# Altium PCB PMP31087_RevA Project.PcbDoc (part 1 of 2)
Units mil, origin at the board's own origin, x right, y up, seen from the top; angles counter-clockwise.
Board outline 6012.5 x 1662.5 mil, 2 copper layers (Top Layer, Bottom Layer), stack 62 mil thick; 71 components, 40 nets, 159 pads, 54 vias.
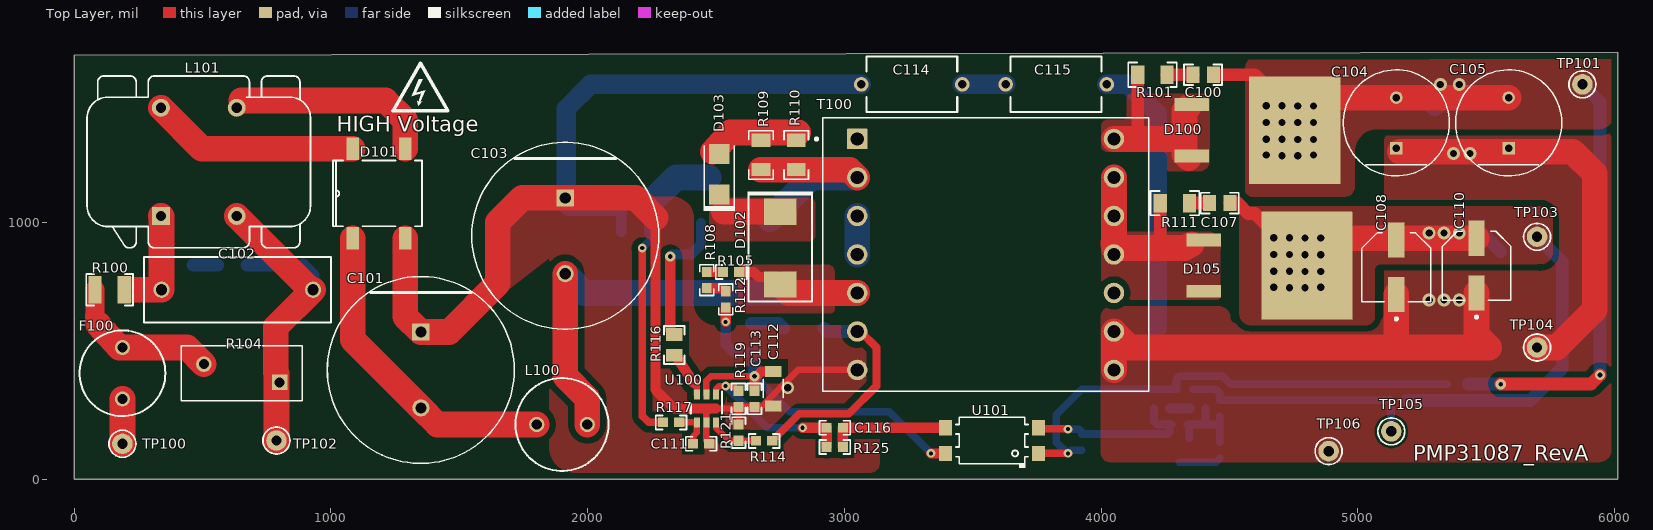
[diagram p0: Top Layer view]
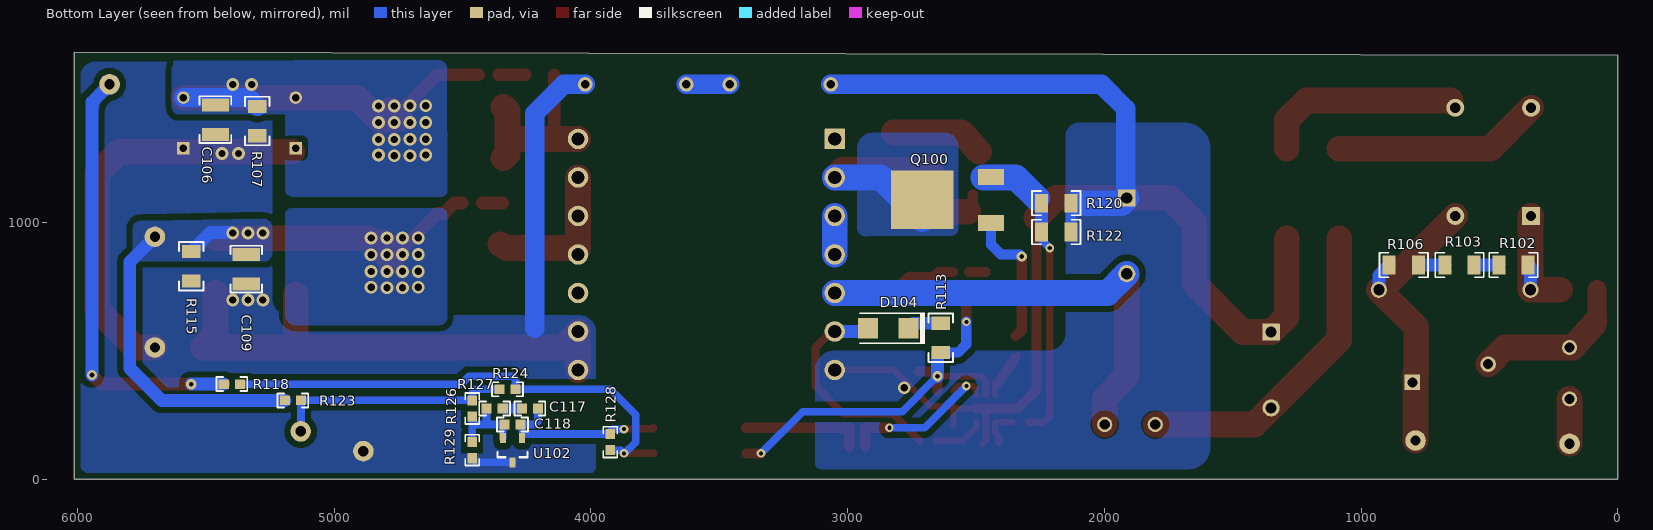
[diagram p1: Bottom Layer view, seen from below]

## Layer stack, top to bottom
Top Solder: solder mask 0.4, Solder Resist, Dk 3.5
Top Layer: signal copper 1.4
Dielectric1: core 59.2, FR-4 High Tg, Dk 4.8
Bottom Layer: signal copper 1.4
Bottom Solder: solder mask 0.4, Solder Resist, Dk 3.5

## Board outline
0,0 0,1650 6012.5,1662.5 6012.5,0

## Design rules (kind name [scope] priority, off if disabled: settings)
AcuteAngle [All] p1: minimum=4.50000000000000E+0001 checktracksonly=FALSE
AssemblyTestPointUsage [All] p1: valid=2
BoardOutlineClearance BoardOutlineClearance_MountingHoles [OnCopper and InComponentClass('Mounting Holes')] p1: gap=39.37 ignorepadtopadclearanceinfootprint=FALSE
BoardOutlineClearance BoardOutlineClearance_Poly [OnCopper and IsPoly] p2: gap=25 ignorepadtopadclearanceinfootprint=FALSE
BoardOutlineClearance [OnCopper and Not InComponentClass('Logo') and not InComponentClass('FiducialMark') and not InRegion(1000,500,4000,800) and not InPoly] p3: gap=40 ignorepadtopadclearanceinfootprint=FALSE
Clearance Clearance_Keepouts [((IsTrack Or IsArc) And Not InPoly) And IsFree and IsKeepOut vs ((IsTrack Or IsArc) And Not InPoly) And IsFree and IsKeepOut] p1: gap=0 ignorepadtopadclearanceinfootprint=FALSE
Clearance Clearance_Poly [InPolygon] p2: gap=25 ignorepadtopadclearanceinfootprint=TRUE
Clearance Clearance_FiducialMark [IsKeepOut and InComponentClass('FiducialMark') vs IsPad and InComponentClass('FiducialMark')] p3: gap=0 ignorepadtopadclearanceinfootprint=FALSE
Clearance [All] p4: gap=7.87 ignorepadtopadclearanceinfootprint=TRUE
ComponentClearance ComponentClearance_MountingHoles_FiducialMarks [InComponentClass('Mounting Holes') vs InComponentClass('FiducialMark')] p1: gap=50 collisioncheckmode=3 verticalgap=10 showdistances=FALSE
ComponentClearance ComponentClearance_Shunt [InComponentClass('Header') vs InComponentClass('Shunt')] p2: gap=0 collisioncheckmode=3 verticalgap=0 showdistances=FALSE
ComponentClearance ComponentClearance_Logo [InComponentClass('Logo')] p3: gap=30 collisioncheckmode=3 verticalgap=10 showdistances=FALSE
ComponentClearance ComponentClearance_ScrewToNut [(HasFootprint('NY PMS 440 0025 PH')) vs (HasFootprint('Keystone_1902C'))] p4: gap=5 collisioncheckmode=3 verticalgap=10 showdistances=FALSE
ComponentClearance ComponentClearance_MountingHoles [InComponentClass('Mounting Holes')] p5: gap=100 collisioncheckmode=3 verticalgap=100000 showdistances=FALSE
ComponentClearance ComponentClearance_SmallPassives [HasFootprint('0201*') or HasFootprint('0402*') or HasFootprint('0508') or HasFootprint('0603*') or HasFootprint('0612') or HasFootprint('0805*') or HasFootprint('0815*') or HasFootprint('0830*') or HasFootprint('1206*') or HasFootprint('1210*') or HasFootprint('1808*') or HasFootprint('1812*') or HasFootprint('1825*') or HasFootprint('2010*') or HasFootprint('2220*') or HasFootprint('2225*') or HasFootprint('2512*') or HasFootprint('2728*') or HasFootprint('3518*') vs HasFootprint('0201*') or HasFootprint('0402*') or HasFootprint('0508') or HasFootprint('0603*') or HasFootprint('0612') or HasFootprint('0805*') or HasFootprint('0815*') or HasFootprint('0830*') or HasFootprint('1206*') or HasFootprint('1210*') or HasFootprint('1808*') or HasFootprint('1812*') or HasFootprint('1825*') or HasFootprint('2010*') or HasFootprint('2220*') or HasFootprint('2225*') or HasFootprint('2512*') or HasFootprint('2728*') or HasFootprint('3518*')] p6: gap=14.96 collisioncheckmode=3 verticalgap=10 showdistances=FALSE
ComponentClearance ComponentClearance_THtoSMT [IsThruComponent vs IsSMTComponent] p7: gap=30 collisioncheckmode=3 verticalgap=30 showdistances=FALSE
ComponentClearance ComponentClearance_THtoTH [IsThruComponent vs IsThruComponent] p8: gap=20 collisioncheckmode=3 verticalgap=30 showdistances=FALSE
ComponentClearance [All] p9: gap=20 collisioncheckmode=3 verticalgap=10 showdistances=FALSE
DiffPairsRouting [All] p1: maxlimit=100 minlimit=10 mostfreqgap=10 toplayer_minwidth=15 toplayer_maxwidth=15 toplayer_prefwidth=15 bottomlayer_minwidth=15 bottomlayer_maxwidth=15 bottomlayer_prefwidth=15 maxuncoupledlength=1000
FabricationTestPointUsage TestPointUsage [All] p1: valid=2 allowmultiple=FALSE
FabricationTestpoint Testpoint [All] p1: side=3 testpointundercomponent=TRUE minsize=40 maxsize=100 preferedsize=60 minholesize=0 maxholesize=40 preferedholesize=32 testpointgrid=1 allowsidetop=TRUE allowsidebottom=TRUE usegrid=TRUE gridtolerance=0.01
FanoutControl Fanout_LCC [IsLCC] p1: bgadir=Out bgaviamode=Centered fanoutstyle=Auto fanoutdirection=Alternating viagrid=1 // Fanout_LCC (Default Rule)
FanoutControl Fanout_BGA [IsBGA] p2: bgadir=Out bgaviamode=Centered fanoutstyle=Auto fanoutdirection=Alternating viagrid=1 // Fanout_BGA (Default Rule)
FanoutControl Fanout_Default [All] p4: bgadir=Out bgaviamode=Centered fanoutstyle=Auto fanoutdirection=Alternating viagrid=1 // Fanout_Default (Default Rule)
FanoutControl Fanout_Small [(CompPinCount < 5)] p5: bgadir=Out bgaviamode=Centered fanoutstyle=Auto fanoutdirection=OutThenIn viagrid=1 // Fanout_Small (Default Rule)
Height [All] p1: minheight=0 maxheight=1500 prefheight=500
HoleSize [All] p1: absolutevalues=TRUE maxlimit=251 minlimit=7.87 maxpercent=80.000 minpercent=20.000
MinimumAnnularRing MinimumAnnularRing_ThermalPadVias [IsVia and InAnyComponent] p1: minimumring=5.91
MinimumAnnularRing [All] p2: minimumring=7.87
MinimumSolderMaskSliver MinimumSolderMaskSliver_Logo [InComponentClass('Logo') vs InComponentClass('Logo')] p1: minsoldermaskwidth=0.7
MinimumSolderMaskSliver [All] p2: minsoldermaskwidth=3.94
PlaneConnect [All] p1: planeconnectstyle=Relief reliefexpansion=10 reliefentries=4 reliefconductorwidth=10 reliefairgap=10
PolygonConnect [All] p1: connectstyle=Direct reliefconductorwidth=10 reliefentries=4 polygonreliefangle="90 Angle" airgapwidth=10
RoutingVias ThermalPadVias [IsVia and InAnyComponent] p1: holewidth=7.87 width=19.68 viastyle="Through Hole" minholewidth=7.87 minwidth=19.68 maxholewidth=12.99 maxwidth=23.62
RoutingVias [All] p2: holewidth=16 width=34 viastyle="Through Hole" minholewidth=7.87 minwidth=24 maxholewidth=40 maxwidth=65
SilkToBoardRegionClearance [Not ((IsComment or IsDesignator) And (Hide <> 'False')) and not InRegion(1000,500,4000,800)] p1:
SilkToSilkClearance SilkToSilkClearance_Pb-FreeLogo [(HasFootprint('Pb-Free_Overlay_Medium') OR HasFootprint('Pb-Free_Overlay_Small')) vs (HasFootprint('Pb-Free_Overlay_Medium') OR HasFootprint('Pb-Free_Overlay_Small'))] p1 off: silktosilkclearance=0
SilkToSilkClearance [All] p2 off: silktosilkclearance=3.94
SilkToSolderMaskClearance SilkToComponentPadClearance [(IsPad or IsFill or IsRegion) and InAnycomponent] p1: minsilkscreentomaskgap=5 clearancetoexposedcopper=TRUE
SilkToSolderMaskClearance "Silk to Solder Mask Opening" [All] p2: minsilkscreentomaskgap=3.94 clearancetoexposedcopper=FALSE
SolderMaskExpansion [All] p1: expansion=1.97 istentingtop=FALSE
UnRoutedNet [All] p1: checkbadconnections=TRUE
Width [All] p1: maxlimit=100 minlimit=6 preferedwidth=10 checkconnectedcopper=TRUE
13 further rules are at their usual default settings.

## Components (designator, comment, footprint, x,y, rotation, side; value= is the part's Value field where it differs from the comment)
C100 "" 0805_HV 4397.5,1575 r0 top
C101 "860241381004" FP-860241381004_RADIAL-MFG 1350,425 r270 top value=33µF
C102 "890324025027CS" WCAP-FTX2_1800x600x1150 635.14,737.5 r0 top value=0.22uF
C103 "860241381004" FP-860241381004_RADIAL-MFG 1912.5,947.64 r270 top value=33µF
C104 "25ZL680MEFC10X20" FP-25ZL680MEFC10X20_RADIAL-MFG 5150,1387.5 r90 top value=680µF
C105 "25ZL680MEFC10X20" FP-25ZL680MEFC10X20_RADIAL-MFG 5587.5,1387.5 r90 top value=680µF
C106 "GRM32RR71H105KA01L" 1210_200 5462.5,1400 r270 bottom value=DNP
C107 "" 0805_HV 4462.5,1075 r0 top
C108 "DNP" FP-APXJ100ARA391MFA0G_SMD2-MFG 5150,825 r90 top
C109 "GRM32RR71H105KA01L" 1210_200 5342.57,817.38 r270 bottom value=DNP
C110 "APXJ100ARA391MFA0G" FP-APXJ100ARA391MFA0G_SMD2-MFG 5462.5,831.3 r90 top value=390µF
C111 "" 0603 2442.13,137.5 r0 top value=DNP
C112 "C3216X7R1H335K160AC" 1206_190 2722.8,352.2 r270 top value=3.3uF
C113 "C1608X7R1H104K080AA" 0603 2650,312.5 r270 top value=0.1uF
C114 "" C900_9x13 3262.5,1537.5 r180 top value=2200pF
C115 "C921U222MVVDBA7317" C900_9x13 3825,1537.5 r180 top value=2200pF
C116 "C0603C682K5RACTU" 0603 2962.5,200 r180 top value=6800pF
C117 "" 0603 4237.5,275 r0 bottom value=DNP
C118 "GRM188R71H224KAC4D" 0603 4305.41,212.5 r180 bottom value=0.22uF
D100 "MBRB20100CTT4G" DDPAK 4598.62,1358.73 r0 top value=100V
D101 "DF08SA" DF-S 1187.5,1112.5 r90 top value=800V
D102 "SMCJ110A" SMC_265 2750,900 r270 top value=110V
D103 "US1J-13-F" SMA 2512.5,1187.5 r90 top value=600V
D104 "US1D-E3/61T" SMA 2841.93,587.5 r0 bottom value=200V
D105 "MBRB2060CTT4G" DDPAK 4646.06,831.3 r0 top value=60V
F100 "37212000001" FUSE_372 187.5,412.2 r270 top
"HIGH Voltage" "DANGER HIGH VOLTAGE" IEC_HighVoltage_Small 1348.5,1522.5 r0 top
L100 "744732470" WE-TI_8075_STU 1900,212.5 r0 top value=47uH
L101 "744823220" WE-CMB_M 485.14,1235.63 r90 top value=20mH
Q100 "IPD60R600P7SAUMA1" DPAK 2575,1087.5 r0 bottom value=600V
R100 "CRCW12100000Z0EAHP" 1210 137.5,737.5 r0 top value=0
R101 "DNP" 1206 4200,1575 r180 top
R102 "CRCW12061M50JNEA" 1206 406,833.75 r180 bottom value=1.5Meg
R103 "CRCW12061M50JNEA" 1206 616.25,833.75 r180 bottom value=1.5Meg
R104 "B72210S2271K101" FP-B72210S2271K101_RADIAL-MFG 652.5,412.2 r180 top
R105 "CRCW06034M99FKEA" 0603 2558.9,806.5 r0 top value=4.99Meg
R106 "CRCW12061M50JNEA" 1206 833.75,833.75 r180 bottom value=1.5Meg
R107 "DNP" 1206 5300,1394.59 r90 bottom
R108 "CRCW06034M99FKEA" 0603 2463.9,775 r90 top value=4.99Meg
R109 "DNP" 1206 2675,1262.5 r90 top
R110 "RC1206FR-0749R9L" 1206 2812.5,1262.5 r90 top value=49.9
R111 "DNP" 1206 4287.5,1075 r180 top
R112 "CRCW06034M99FKEA" 0603 2537.5,700 r90 top value=4.99Meg
R113 "CRCW120622R0JNEA" 1206 2637.5,550 r270 bottom value=22
R114 "CRCW0603147KFKEA" 0603 2687.5,148.62 r0 top value=147k
R115 "DNP" 1206 5557.04,828.73 r90 bottom
R116 "CRCW080510R0JNEA" 0805_HV 2337.5,522.5 r90 top value=10
R117 "CRCW06031K69FKEA" 0603 2325,220.87 r180 top value=1.69k
R118 "CRCW06034K02FKEA" 0603 5398.67,369.75 r180 bottom value=DNP
R119 "CRCW06034K02FKEA" 0603 2587.5,312.5 r90 top value=4.02k
R120 "ERJ-8RQFR39V" 1206 2187.5,1075 r0 bottom value=0.39
R121 "CRCW060340K2FKEA" 0603 2587.5,180.51 r270 top value=40.2k
R122 "ERJ-8RQFR39V" 1206 2187.5,962.5 r0 bottom value=0.39
R123 "CRCW060349R9FKEA" 0603 5160.67,306.5 r0 bottom value=49.9
R124 "CRCW06031K00FKEA" 0603 4325,350 r0 bottom value=1.00k
R125 "CRCW060332K4FKEA" 0603 2962.5,125 r0 top value=32.4k
R126 "RC0603FR-0761K9L" 0603 4462.5,275 r90 bottom value=61.9k
R127 "CRCW06034K02FKEA" 0603 4375,275 r180 bottom value=DNP
R128 "CRCW06031K00FKEA" 0603 3925,144 r270 bottom value=1.00k
R129 "CRCW060320K0FKEA" 0603 4462.5,112.5 r90 bottom value=20.0k
T100 "750319816" FP-750319816_PTH_TRANSFORMER_32MM25_27MM05-MFG 3550,875 r0 top
TP100 "5000" Keystone5000 187.5,137.5 r0 top
TP101 "5000" Keystone5000 5875,1537.5 r0 top
TP102 "5000" Keystone5000 787.5,150 r0 top
TP103 "5000" Keystone5000 5698.5,943.75 r0 top
TP104 "5001" Keystone5001 5698.5,512.5 r0 top
TP105 "5000" Keystone5000 5130.5,185.71 r90 top
TP106 "5001" Keystone5001 4886.5,108.75 r90 top
U100 "UCC28742DBVR" DBV0006A_N 2462.5,275 r270 top
U101 "FOD817ASD" N04C 3575,150 r180 top
U102 "ATL431LIBQDBZR" DBZ0003A_N 4305.41,112.5 r270 bottom

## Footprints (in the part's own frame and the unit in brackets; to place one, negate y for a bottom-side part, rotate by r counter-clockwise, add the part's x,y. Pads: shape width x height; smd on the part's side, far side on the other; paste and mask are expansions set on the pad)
0603 [mm] "0603 from SM-752 data"
  rect 1x0.95 smd: 1(-0.8,0) 2(0.8,0)
  silkscreen extent -1.52,-0.69 1.52,0.69, body extent -0.87,-0.47 0.87,0.47, height 1
0805_HV [mil] "0805 with 30mil clearance between pads"
  rect 50x63 smd: 1(-40,0) 2(40,0)
  silkscreen extent -74,-40 74,40, body extent -43,-29 43,29, height 57
1206 [mm] "1206 from SM-752 data"
  rect 1.3x1.85 smd: 1(-1.45,0) 2(1.45,0)
  silkscreen extent -2.4,-1.21 2.4,1.21, body extent -1.7,-0.9 1.7,0.9, height 1.35
1206_190 [mm] "1206_190"
  rect 1.1x1.6 smd: 1(-1.7,0) 2(1.7,0)
  silkscreen extent -0.9,-1 0.9,1, body extent -1.75,-0.95 1.75,0.95, height 1.9
1210 [mm] "1210 from SM-752 data"
  rect 1.3x2.7 smd: 1(-1.45,0) 2(1.45,0)
  silkscreen extent -2.32,-1.57 2.32,1.57, body extent -1.7,-1.35 1.7,1.35, height 1.35
1210_200 [mm] "1210"
  rect 1.3x2.7 smd: 1(-1.45,0) 2(1.45,0)
  silkscreen extent -2.32,-1.57 2.32,1.57, body extent -1.7,-1.35 1.7,1.35, height 2
C900_9x13 [mm] "Kemet"
  round 1.45 hole 0.85: 1(-5,0) 2(5,0)
  silkscreen extent -4.5,-2.75 4.5,2.75, body extent -4.49,-2.75 4.49,2.75, height 12.96
DBV0006A_N [mm] "SOT23, 6-Leads, Body 2.9x1.6mm, Pitch 0.95mm, Lead Span 2.8mm, IPC Medium Density"
  rrect17% 1x0.6 smd: 1(-1.375,0.95) 2(-1.375,0) 3(-1.375,-0.95) 4(1.375,-0.95) 5(1.375,0) 6(1.375,0.95)
  silkscreen extent -1.68,-1.55 0.5,1.55, body extent -1.42,-1.46 1.42,1.46, height 1.12
DBZ0003A_N [mm] "SOT23, 3-Leads, Body 2.9x1.3mm, Pitch 0.95mm, Lead Span 2.4mm, IPC Medium Density"
  rrect17% 1x0.6 smd: 1(-1.2,0.95) 2(-1.2,-0.95) 3(1.2,0)
  silkscreen extent 0.2,-1.5 0.7,1.5, body extent -1.26,-1.46 1.26,1.46, height 0.98
DDPAK [mil] "D2-PAK, 3-Pads, Body 9.7x10.4mm (max), TO-263AB, using Vishay Silionix recommended pad sizes"
  rrect8% 135x49.49 smd: 1(-246.06,100) 3(-246.06,-100)
  rrect1% 355x420 smd paste-181.1: 2(155.51,0)
  body extent -295,-202 324,202, height 180
DF-S [mil] "Diodes Inc. recommended land pattern per ap02001.pdf rev 30"
  rect 88x49 smd: 1(-174.5,102.36) 2(-174.5,-102.36) 3(174.5,-102.36) 4(174.5,102.36)
  silkscreen extent -128,-168 128,180, body extent -205,-168 205,168, height 108
DPAK [mm] "D-PAK, 3-Pads, Body 6.22x6.73mm (max), TO-252AA using nominal STEP model"
  rrect6% 2.6x1.6 smd: 1(-3.4,2.28) 3(-3.4,-2.28)
  rrect2% 6.2x5.8 smd paste-3: 2(3.4,0)
  body extent -3.86,-3.29 5.84,3.29, height 2.48
FP-25ZL680MEFC10X20_RADIAL-MFG [mm]
  rrect8% 1.25x1.25 hole 0.75 paste-1000 mask+0: 1(-2.5,0)
  round 1.25 hole 0.75 paste-1000 mask+0: 2(2.5,0)
  silkscreen extent -5.25,-5.25 5.25,5.25, body extent -5.35,-5.35 5.35,5.35, height 0.25
FP-750319816_PTH_TRANSFORMER_32MM25_27MM05-MFG [mm]
  rrect5% 2.02x2.02 hole 1.32 paste-1000 mask+0: 1(-12.7,11.43)
  round 2.02 hole 1.32 paste-1000 mask+0: 2(-12.7,7.62) 3(-12.7,3.81) 4(-12.7,0) 5(-12.7,-3.81) 6(-12.7,-7.62) 7(-12.7,-11.43) 8(12.7,-11.43) 9(12.7,-7.62) 10(12.7,-3.81) 11(12.7,0) 12(12.7,3.81) 13(12.7,7.62) 14(12.7,11.43)
  silkscreen extent -16.85,-13.52 16.12,13.52, body extent -16.22,-13.62 16.22,13.62, height 0.25
FP-860241381004_RADIAL-MFG [mm]
  rrect6% 1.7x1.7 hole 1.1 paste-1000 mask+0: 1(-3.75,0)
  round 1.7 hole 1.1 paste-1000 mask+0: 2(3.75,0)
  silkscreen extent -9.25,-9.25 9.25,9.25, body extent -9.35,-9.35 9.35,9.35, height 0.25
FP-APXJ100ARA391MFA0G_SMD2-MFG [mm]
  rrect6% 3.5x1.6 smd paste+0 mask+0: 1(-2.7,0) 2(2.7,0)
  silkscreen extent -5.22,-3.4 3.4,3.4, body extent -4.7,-3.65 4.7,3.65, height 0.25
FP-B72210S2271K101_RADIAL-MFG [mm]
  rrect6% 1.55x1.55 hole 1 paste-1000 mask+0: 1(-3.75,0.9)
  round 1.55 hole 1 paste-1000 mask+0: 2(3.75,-0.9)
  silkscreen extent -6,-2.7 6,2.7, body extent -6.1,-2.8 6.1,2.8, height 0.25
FUSE_372 [mm] "LITTELFUSE"
  round 1.5 hole 1: 1(-2.54,0) 2(2.54,0)
  silkscreen extent -4.25,-4.25 4.25,4.25, body extent -4.25,-4.25 4.25,4.25, height 8
IEC_HighVoltage_Small [mil]
  silkscreen extent -107,-88 107,97
Keystone5000 [mil] "For Keystone 500x miniature loop terminals"
  round 80 hole 40: 1(0,0)
  silkscreen extent -52,-52 52,52, body extent -49,-49 49,49, height 182
Keystone5001 [mil] "For Keystone 500x miniature loop terminals"
  round 80 hole 40: 1(0,0)
  silkscreen extent -52,-52 52,52, body extent -49,-49 49,49, height 182
N04C [mm] "FAIRCHILD"
  rect 1.3x1.5 smd mask+0.065: 1(-4.587,1.27) 2(-4.612,-1.27) 3(4.588,-1.27) 4(4.613,1.27)
  silkscreen extent -3.56,-2.3 3.56,2.72, body extent -5.08,-2.3 5.08,2.3, height 3.87
SMA [mm] "Molded Diode, 2-Leads, Body 4.3x2.6mm, IPC Medium Density, based on OnSemi component dimensions and land pattern"
  rect 2x2 smd: 1(-2,0) 2(2,0)
  silkscreen extent -3.66,-1.57 2.79,1.57, body extent -2.6,-1.3 2.6,1.3, height 2.42
SMC_265 [mm] "SMD, 2-Leads, Body 7.15x6.25mm"
  rect 2.6x3.2 smd: 1(-3.6,0) 2(3.6,0)
  silkscreen extent -5.6,-3.23 5.3,3.22, body extent -4.08,-3.13 4.08,3.13, height 2.65
WCAP-FTX2_1800x600x1150 [mm] "TH, 2-Leads, Body 18x6mm, Lead Spacing 15mm"
  round 1.6 hole 1.1: 1(-7.5,0) 2(7.5,0)
  silkscreen extent -9.25,-3.25 9.25,3.25, body extent -9.25,-3.25 9.25,3.25, height 12
WE-CMB_M [mil] "Wurth"
  rect 70x70 hole 40: 1(-210.63,147.64)
  round 70 hole 40: 2(-210.63,-147.64) 3(210.63,-147.64) 4(210.63,147.64)
  silkscreen extent -335,-435 335,435, body extent -335,-394 335,394, height 1044
WE-TI_8075_STU [mm] "TH, 2-Leads, Dia 9.5mm, Pin Spacing 5mm"
  round 1.5 hole 1: 1(-2.5,0) 2(2.5,0)
  silkscreen extent -4.6,-4.6 4.6,4.6, body extent -5.8,-5.8 5.8,5.8, height 9.7

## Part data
C100 C107: library part CMP-0008225-2, "CAP, CERM, +/- 10%, X7R, 0805", Cap_Case=0805, Manufacturer=MuRata, TempCo=X7R, Tolerance_%=10%, Value1=Unknown
C101 C103: library part CMP-0093307-1, "33 µF 400 V Aluminum Electrolytic Capacitors Radial, Can - 10000 Hrs @ 105°C", Digikey Part Number=732-9303-1-ND, Leakage Current=628uA, Manufacturer="Wurth Electronics", Mouser Part Number=710-860241381004, Operating Temperature Range="-25°C to +105°C", Tolerance_%=20%, ValueDisplayed=33uF
C102: library part CMP-0012315-3, "CAP, Film, 0.22 uF, 275 V, +/- 10%, TH", Cap_Case=18x11.5x6mm, Manufacturer="Wurth Elektronik", Supplier Part Number 1=732-5802-ND, Tolerance_%=10%, Value1=Unknown, Value2=275V, ValueDisplayed=0.22uF
C104 C105: library part CMP-0092158-1, "Aluminum Electrolytic Capacitors Radial, Can - 4000 Hrs @ 105°C 680UF 25V", Digikey Part Number=1189-3993-ND, Leakage Current=170uA, Manufacturer=Rubycon, Mouser Part Number=232-25ZL680MEFC10X20, Operating Temperature Range="-40°C to +105°C", Tolerance_%=20%, ValueDisplayed=680uF
C106 C109: library part CMP-0009251-1, "CAP, CERM, 1 uF, +/- 10%, X7R, 1210", Cap_Case=1210, Manufacturer=MuRata, Supplier Part Number 1=490-1863-1-ND, TempCo=X7R, Tolerance_%=10%, Value1="0.003 ohm", ValueDisplayed=DNP
C108: library part CMP-0092160-1, "Capacitors Radial", Digikey Part Number=565-APXJ100ARA391MFA0GCT-ND, Leakage Current=1950uA, Operating Temperature Range="-55°C to +105°C", Tolerance_%=20%
C110: library part CMP-0092160-1, "Aluminum - Polymer Capacitors Radial, Can - SMD 13mOhm 15000 Hrs @ 105°C", Digikey Part Number=565-APXJ100ARA391MFA0GCT-ND, Leakage Current=1950uA, Manufacturer="United Chemi-Con", Mouser Part Number=661-XJ100ARA391MFA0G, Operating Temperature Range="-55°C to +105°C", Tolerance_%=20%, ValueDisplayed=390uF
C111 C117: library part CMP-0007465-1, "CAP, CERM, +/- 10%, X7R, 0603", Cap_Case=0603, Manufacturer=MuRata, PartNumber=DNP, Supplier Part Number 1=490-1510-1-ND, TempCo=X7R, Tolerance_%=10%, Value1=Unknown
C112: library part CMP-0008700-1, "CAP, CERM, 3.3 uF, 50 V, +/- 10%, X7R, 1206_190", Cap_Case=1206, Manufacturer=TDK, Supplier Part Number 1=445-5990-1-ND, TempCo=X7R, Tolerance_%=10%, Value1=Unknown, Value2=50V, ValueDisplayed=3.3uF
C113: library part CMP-0007044-1, "CAP, CERM, 0.1 uF, 50 V, +/- 10%, X7R, 0603", Cap_Case=0603, Manufacturer=TDK, Supplier Part Number 1=445-1314-1-ND, TempCo=X7R, Tolerance_%=10%, Value1="0.0296 ohm", Value2=50V, ValueDisplayed=0.1uF
C114: library part CMP-0078358-1, "CAP, CERM, 2200 pF, X1 400 VAC/Y1 400 VAC, +/- 20%, Y5V, D9xL13mm", Cap_Case=9x13mm, Manufacturer=Kemet, Supplier Part Number 1=399-9487-1-ND, TempCo=Y5V, Tolerance_%=20%, ValueDisplayed=SHORT
C115: library part CMP-0078358-1, "CAP, CERM, 2200 pF, X1 400 VAC/Y1 400 VAC, +/- 20%, Y5V, D9xL13mm", Cap_Case=9x13mm, Manufacturer=Kemet, Supplier Part Number 1=399-9487-1-ND, TempCo=Y5V, Tolerance_%=20%, ValueDisplayed=2200pF
C116: library part CMP-0006963-3, "CAP, CERM, 6800 pF, 50 V, +/- 10%, X7R, 0603", Cap_Case=0603, Manufacturer=Kemet, Supplier Part Number 1=399-1089-1-ND, TempCo=X7R, Tolerance_%=10%, Value1=Unknown, Value2=50V, ValueDisplayed=6800pF
C118: library part CMP-0007445-1, "CAP, CERM, 0.22 uF, 50 V, +/- 10%, X7R, 0603", Cap_Case=0603, Manufacturer=MuRata, Supplier Part Number 1=490-12546-1-ND, TempCo=X7R, Tolerance_%=10%, Value1=Unknown, Value2=50V, ValueDisplayed=0.22uF
D100: library part CMP-0028499-3, "Diode, Schottky, 100 V, 20 A, DDPAK", Manufacturer="ON Semiconductor", Value1=20A, Value2=0.95V
D101: library part CMP-0029205-3, "Diode, Switching-Bridge, 800 V, 1 A, DF-S", Manufacturer=Vishay-Semiconductor, Value1=1A, Value2=1.1V
D102: library part CMP-0005731-1, "Diode, TVS, Uni, 110 V, SMC", Manufacturer=Littelfuse, Power_W=6.5W, Supplier Part Number 1=SMCJ110ALFCT-ND
D103: library part CMP-0077027-2, "Diode, Ultrafast, 600 V, 1 A, SMA", Manufacturer="Diodes Inc.", Value1=1A, Value2=1.7V
D104: library part CMP-0029189-1, "Diode, Ultrafast, 200 V, 1 A, AEC-Q101, SMA", Manufacturer=Vishay-Semiconductor, Supplier Part Number 1=US1D-E3/61TGICT-ND, Value1=1A, Value2=1V
D105: library part CMP-0028501-3, "Diode, Schottky, 60 V, 20 A, DDPAK", Manufacturer="ON Semiconductor", Value1=20A, Value2=0.95V
F100: library part CMP-0003555-1, "Fuse, 2 A, 250VAC/VDC, TH", Irating_A=2A, Manufacturer=Littelfuse, Supplier Part Number 1=WK4257CT-ND
"HIGH Voltage": library part CMP-0074835-1, "IEC 61010-1 High Voltage Warning"
L100: library part CMP-0064737-2, "Inductor, Unshielded Drum Core, Metal Composite, 47 uH,", Manufacturer="Wurth Elektronik", PartNumber=744732681, Supplier Part Number 1=732-3753-ND, ValueDisplayed=47uH
L101: library part CMP-0013122-2, "Coupled inductor, 20 mH, 1.5 A, 0.27 ohm, TH", Manufacturer="Wurth Elektronik", Supplier Part Number 1=732-1448-ND, ValueDisplayed=20mH
Q100: library part CMP-0081319-2, "MOSFET, N-CH, 600 V, 6 A, DPAK", Alternate Manufacturer=None, Manufacturer="Infineon Technologies", Supplier Part Number 1=IPD60R600P7SAUMA1CT-ND, Value1="? ohm", Value2="9 nC"
R100: library part CMP-0015017-1, "RES, 0, 1%, 0.75 W, AEC-Q200 Grade 0, 1210", Manufacturer=Vishay-Dale, Power_W=750mW, Supplier Part Number 1=541-0.0NCT-ND, TempCo=ppm/C, Tolerance_%=1%, Value2=0.75W, Value_Code=0
R101 R107 R109 R111 R115: library part CMP-0018328-1, "RES, 0.25 W, 1206", Manufacturer="Yageo America", Power_W=250mW, Supplier Part Number 1=311-49.9FRCT-ND, TempCo="100 ppm/C", Tolerance_%=1%, Value2=0.25W, Value_Code=49R9
R102 R103 R106: library part CMP-0018614-2, "RES, 1.5 M, 5%, 0.25 W, 1206", Manufacturer=Vishay-Dale, Power_W=250mW, Supplier Part Number 1=541-1.5MECT-ND, TempCo="200 ppm/C", Tolerance_%=5%, Value2=0.25W, Value_Code=1M50, ValueDisplayed=1.5M
R104: library part CMP-0090587-1, "VARISTOR 430V 3.5KA DISC 10MM", Clamping Voltage=710V, Digikey Part Number=495-1433-ND, Manufacturer=EPCOS, Mouser Part Number=871-B72210S2271K101, Operating Temperature Range="-40°C to +105°C", ValueDisplayed=220pF, Varistor Voltage=430V, Voltage Tolerance=10%
R105 R108 R112: library part CMP-0022468-2, "RES, 4.99 M, 1%, 0.1 W, 0603", Manufacturer=Vishay-Dale, Power_W=100mW, Supplier Part Number 1=541-4.99MHCT-ND, TempCo="100 ppm/C", Tolerance_%=1%, Value2=0.1W, Value_Code=4M99, ValueDisplayed=4.99M
R110: library part CMP-0018328-1, "RES, 49.9, 1%, 0.25 W, 1206", Manufacturer="Yageo America", Power_W=250mW, Supplier Part Number 1=311-49.9FRCT-ND, TempCo="100 ppm/C", Tolerance_%=1%, Value2=0.25W, Value_Code=49R9, ValueDisplayed=49.9
R113: library part CMP-0018631-3, "RES, 22, 5%, 0.25 W, AEC-Q200 Grade 0, 1206", Manufacturer=Vishay-Dale, Power_W=250mW, Supplier Part Number 1=541-22ECT-ND, TempCo="200 ppm/C", Tolerance_%=5%, Value2=0.25W, Value_Code=22R0, ValueDisplayed=22
R114: library part CMP-0022052-3, "RES, 147 k, 1%, 0.1 W, 0603", Manufacturer=Vishay-Dale, Power_W=100mW, Supplier Part Number 1=541-147KHCT-ND, TempCo="100 ppm/C", Tolerance_%=1%, Value2=0.1W, Value_Code=147k
R116: library part CMP-0020448-1, "RES, 10, 5%, 0.125 W, 0805", Manufacturer=Vishay-Dale, Power_W=125mW, Supplier Part Number 1=541-10ACT-ND, TempCo="200 ppm/C", Tolerance_%=5%, Value2=0.125W, Value_Code=10R0, ValueDisplayed=10
R117: library part CMP-0022131-2, "RES, 1.69 k, 1%, 0.1 W, 0603", Manufacturer=Vishay-Dale, Power_W=100mW, Supplier Part Number 1=541-1.69KHCT-ND, TempCo="100 ppm/C", Tolerance_%=1%, Value2=0.1W, Value_Code=1k69, ValueDisplayed=1.69k
R118 R127: library part CMP-0022449-1, "RES, 1%, 0.1 W, 0603", Manufacturer=Vishay-Dale, PartNumber=DNP, Power_W=100mW, TempCo="100 ppm/C", Tolerance_%=1%, Value2=0.1W
R119: library part CMP-0022449-1, "RES, 4.02 k, 1%, 0.1 W, 0603", Manufacturer=Vishay-Dale, Power_W=100mW, Supplier Part Number 1=541-4.02KHCT-ND, TempCo="100 ppm/C", Tolerance_%=1%, Value2=0.1W, Value_Code=4k02, ValueDisplayed=4.02k
R120: library part CMP-0017789-2, "RES, 0.39, 1%, 0.25 W, 1206", Manufacturer=Panasonic, Power_W=250mW, Supplier Part Number 1=P.39RCT-ND, TempCo="250 ppm/C", Tolerance_%=1%, Value2=0.25W, Value_Code=R390, ValueDisplayed=0.39
R121: library part CMP-0022410-3, "RES, 40.2 k, 1%, 0.1 W, 0603", Manufacturer=Vishay-Dale, Power_W=100mW, Supplier Part Number 1=541-40.2KHCT-ND, TempCo="100 ppm/C", Tolerance_%=1%, Value2=0.1W, Value_Code=40k2, ValueDisplayed=40.2k
R122: library part CMP-0017789-2, "RES, 0.39, 1%, 0.25 W, 1206", Manufacturer=Panasonic, Power_W=250mW, Supplier Part Number 1=P.39RCT-ND, TempCo="250 ppm/C", Tolerance_%=1%, Value2=0.25W, Value_Code=R390, ValueDisplayed=0.33
R123: library part CMP-0022448-2, "RES, 49.9, 1%, 0.1 W, 0603", Manufacturer=Vishay-Dale, Power_W=100mW, Supplier Part Number 1=541-49.9HCT-ND, TempCo="100 ppm/C", Tolerance_%=1%, Value2=0.1W, Value_Code=49R9, ValueDisplayed=49.9
R124: library part CMP-0022109-4, "RES, 1.00 k, 1%, 0.1 W, 0603", Manufacturer=Vishay-Dale, Power_W=100mW, Supplier Part Number 1=541-1.00KHCT-ND, TempCo="100 ppm/C", Tolerance_%=1%, Value2=0.1W, Value_Code=1k00, ValueDisplayed=TBD
R125: library part CMP-0022334-3, "RES, 32.4 k, 1%, 0.1 W, 0603", Manufacturer=Vishay-Dale, Power_W=100mW, Supplier Part Number 1=541-32.4KHCT-ND, TempCo="100 ppm/C", Tolerance_%=1%, Value2=0.1W, Value_Code=32k4, ValueDisplayed=32.4k
R126: library part CMP-0023216-5, "RES, 61.9 k, 1%, 0.1 W, 0603", Manufacturer=Yageo, Power_W=100mW, Supplier Part Number 1=311-61.9KHRCT-ND, TempCo="100 ppm/C", Tolerance_%=1%, Value2=0.1W, Value_Code=61k9, ValueDisplayed=61.9k
R128: library part CMP-0022109-4, "RES, 1.00 k, 1%, 0.1 W, 0603", Manufacturer=Vishay-Dale, Power_W=100mW, Supplier Part Number 1=541-1.00KHCT-ND, TempCo="100 ppm/C", Tolerance_%=1%, Value2=0.1W, Value_Code=1k00, ValueDisplayed=1.00k
R129: library part CMP-0022204-3, "RES, 20.0 k, 1%, 0.1 W, 0603", Manufacturer=Vishay-Dale, Power_W=100mW, Supplier Part Number 1=541-20.0KHCT-ND, TempCo="100 ppm/C", Tolerance_%=1%, Value2=0.1W, Value_Code=20k0, ValueDisplayed=20.0k
T100: library part CMP-0093376-1, "TRANSFORMER", Frequency_Fixed=70kHz, Manufacturer="Wurth Electronics", Operating Temperature Range="-40°C to +125°C", Voltage_Isolation_Vrms=3kV
TP100 TP101 TP102 TP103 TP105: library part CMP-0055137-1, "Test Point, Miniature, Red, TH", Color=Red, Manufacturer=Keystone, Supplier Part Number 1=36-5000-ND
TP104 TP106: library part CMP-0055138-1, "Test Point, Miniature, Black, TH", Color=Black, Manufacturer=Keystone, Supplier Part Number 1=36-5001-ND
